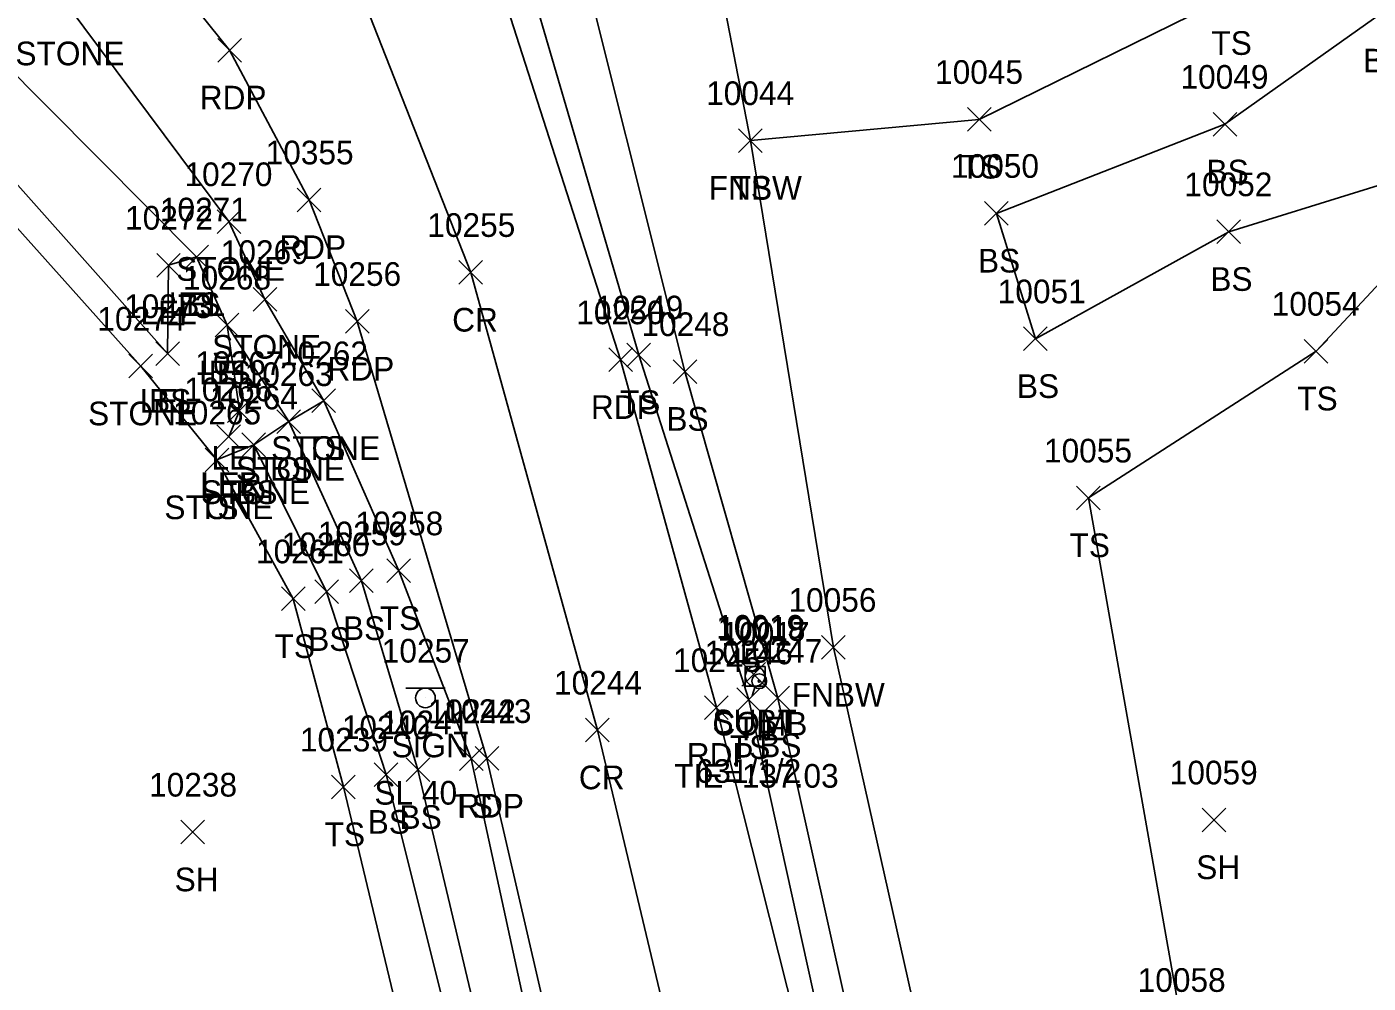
# Model space of a CAD drawing. Extents: x 1475671 to 1477951, y 592661 to 593821.
# Drawn here: x 1476827.5 to 1476940.9, y 592957 to 593037.8 of the extents above; entities that cross this region are included whole.
import ezdxf

# ---------------------------------------------------------------- set-up
doc = ezdxf.new("R2010")
doc.units = 0
for name, color, linetype in [('C_A', 7, 'Continuous'), ('C_C', 7, 'Continuous'), ('C_I', 7, 'Continuous'), ('CBP', 7, 'Continuous'), ('L_A', 7, 'Continuous'), ('L_I', 7, 'Continuous'), ('L_TIC', 7, 'Continuous'), ('LARO', 7, 'Continuous'), ('LASF', 7, 'Continuous'), ('LELB', 7, 'Continuous'), ('LFNC', 7, 'Continuous'), ('P_A', 7, 'Continuous'), ('P_I', 7, 'Continuous'), ('P_TIC', 7, 'Continuous'), ('PET', 7, 'Continuous'), ('PRC', 7, 'Continuous'), ('S_A', 7, 'Continuous'), ('S_C', 7, 'Continuous'), ('S_I', 7, 'Continuous'), ('SSGN', 7, 'Continuous'), ('U_A', 7, 'Continuous'), ('U_C', 7, 'Continuous'), ('U_I', 7, 'Continuous'), ('U_TIC', 7, 'Continuous'), ('UP', 7, 'Continuous')]:
    doc.layers.add(name, color=color, linetype=linetype)

msp = doc.modelspace()

# ---------------------------------------------------------------- linework, layer by layer
at = {"layer": 'CBP'}
for radius in [0.625, 0.0833]:
    msp.add_circle((1476889.41, 592982.47), radius, dxfattribs=at)
at = {"layer": 'L_TIC'}
for points in [[(1476907.01, 593028.94), (1476909.01, 593030.94)], [(1476909.01, 593028.94), (1476907.01, 593030.94)], [(1476927.77, 593028.53), (1476929.77, 593030.53)], [(1476929.77, 593028.53), (1476927.77, 593030.53)], [(1476887.66, 593027.15), (1476889.66, 593029.15)], [(1476889.66, 593027.15), (1476887.66, 593029.15)], [(1476887.66, 593027.15), (1476889.66, 593029.15)], [(1476889.66, 593027.15), (1476887.66, 593029.15)], [(1476843.58, 593020.3), (1476845.58, 593022.3)], [(1476845.58, 593020.3), (1476843.58, 593022.3)], [(1476908.46, 593021), (1476910.46, 593023)], [(1476910.46, 593021), (1476908.46, 593023)], [(1476928.1, 593019.45), (1476930.1, 593021.45)], [(1476930.1, 593019.45), (1476928.1, 593021.45)], [(1476840.85, 593017.32), (1476842.85, 593019.32)], [(1476842.85, 593017.32), (1476840.85, 593019.32)], [(1476840.85, 593017.32), (1476842.85, 593019.32)], [(1476842.85, 593017.32), (1476840.85, 593019.32)], [(1476838.47, 593016.62), (1476840.47, 593018.62)], [(1476840.47, 593016.62), (1476838.47, 593018.62)], [(1476846.62, 593013.72), (1476848.62, 593015.72)], [(1476848.62, 593013.72), (1476846.62, 593015.72)], [(1476843.42, 593011.56), (1476845.42, 593013.56)], [(1476845.42, 593011.56), (1476843.42, 593013.56)], [(1476843.42, 593011.56), (1476845.42, 593013.56)], [(1476845.42, 593011.56), (1476843.42, 593013.56)], [(1476911.75, 593010.4), (1476913.75, 593012.4)], [(1476913.75, 593010.4), (1476911.75, 593012.4)], [(1476838.39, 593009.15), (1476840.39, 593011.15)], [(1476840.39, 593009.15), (1476838.39, 593011.15)], [(1476838.39, 593009.15), (1476840.39, 593011.15)], [(1476840.39, 593009.15), (1476838.39, 593011.15)], [(1476878.22, 593009.04), (1476880.22, 593011.04)], [(1476880.22, 593009.04), (1476878.22, 593011.04)], [(1476935.48, 593009.35), (1476937.48, 593011.35)], [(1476937.48, 593009.35), (1476935.48, 593011.35)], [(1476836.13, 593008.09), (1476838.13, 593010.09)], [(1476838.13, 593008.09), (1476836.13, 593010.09)], [(1476882.12, 593007.63), (1476884.12, 593009.63)], [(1476884.12, 593007.63), (1476882.12, 593009.63)], [(1476844.46, 593004.34), (1476846.46, 593006.34)], [(1476846.46, 593004.34), (1476844.46, 593006.34)], [(1476851.6, 593005.17), (1476853.6, 593007.17)], [(1476853.6, 593005.17), (1476851.6, 593007.17)], [(1476851.6, 593005.17), (1476853.6, 593007.17)], [(1476853.6, 593005.17), (1476851.6, 593007.17)], [(1476851.6, 593005.17), (1476853.6, 593007.17)], [(1476853.6, 593005.17), (1476851.6, 593007.17)], [(1476848.63, 593003.41), (1476850.63, 593005.41)], [(1476850.63, 593003.41), (1476848.63, 593005.41)], [(1476848.63, 593003.41), (1476850.63, 593005.41)], [(1476850.63, 593003.41), (1476848.63, 593005.41)], [(1476843.57, 593002.12), (1476845.57, 593004.12)], [(1476845.57, 593002.12), (1476843.57, 593004.12)], [(1476843.57, 593002.12), (1476845.57, 593004.12)], [(1476845.57, 593002.12), (1476843.57, 593004.12)], [(1476845.68, 593001.44), (1476847.68, 593003.44)], [(1476847.68, 593001.44), (1476845.68, 593003.44)], [(1476845.68, 593001.44), (1476847.68, 593003.44)], [(1476847.68, 593001.44), (1476845.68, 593003.44)], [(1476842.57, 593000.16), (1476844.57, 593002.16)], [(1476844.57, 593000.16), (1476842.57, 593002.16)], [(1476842.57, 593000.16), (1476844.57, 593002.16)], [(1476844.57, 593000.16), (1476842.57, 593002.16)], [(1476916.23, 592996.95), (1476918.23, 592998.95)], [(1476918.23, 592996.95), (1476916.23, 592998.95)], [(1476857.93, 592990.8), (1476859.93, 592992.8)], [(1476859.93, 592990.8), (1476857.93, 592992.8)], [(1476854.78, 592989.95), (1476856.78, 592991.95)], [(1476856.78, 592989.95), (1476854.78, 592991.95)], [(1476851.83, 592989.03), (1476853.83, 592991.03)], [(1476853.83, 592989.03), (1476851.83, 592991.03)], [(1476849.02, 592988.43), (1476851.02, 592990.43)], [(1476851.02, 592988.43), (1476849.02, 592990.43)], [(1476894.68, 592984.33), (1476896.68, 592986.33)], [(1476896.68, 592984.33), (1476894.68, 592986.33)], [(1476887.52, 592979.9), (1476889.52, 592981.9)], [(1476889.52, 592979.9), (1476887.52, 592981.9)], [(1476889.97, 592980.04), (1476891.97, 592982.04)], [(1476891.97, 592980.04), (1476889.97, 592982.04)], [(1476864.07, 592974.92), (1476866.07, 592976.92)], [(1476866.07, 592974.92), (1476864.07, 592976.92)], [(1476859.55, 592973.99), (1476861.55, 592975.99)], [(1476861.55, 592973.99), (1476859.55, 592975.99)], [(1476856.87, 592973.58), (1476858.87, 592975.58)], [(1476858.87, 592973.58), (1476856.87, 592975.58)], [(1476853.26, 592972.53), (1476855.26, 592974.53)], [(1476855.26, 592972.53), (1476853.26, 592974.53)], [(1476926.86, 592969.75), (1476928.86, 592971.75)], [(1476928.86, 592969.75), (1476926.86, 592971.75)], [(1476840.5, 592968.72), (1476842.5, 592970.72)], [(1476842.5, 592968.72), (1476840.5, 592970.72)]]:
    msp.add_lwpolyline(points, dxfattribs=at)
at = {"layer": 'LARO'}
msp.add_lwpolyline([(1476844.57, 593003.12), (1476845.46, 593005.34), (1476844.42, 593012.56), (1476841.85, 593018.32), (1476839.47, 593017.62), (1476839.39, 593010.15)], dxfattribs=at)
at = {"layer": 'LASF'}
for points in [[(1476852.6, 593006.17), (1476849.63, 593004.41), (1476846.68, 593002.44), (1476843.57, 593001.16), (1476837.13, 593009.09), (1476818.53, 593029.85), (1476807.42, 593044.4), (1476779.57, 593058.62), (1476779.42, 593062.14), (1476780.76, 593069.19)], [(1476852.6, 593006.17), (1476847.62, 593014.72), (1476844.58, 593021.3), (1476830.99, 593039.51), (1476813.62, 593055.13), (1476780.76, 593069.19)]]:
    msp.add_lwpolyline(points, dxfattribs=at)
at = {"layer": 'LELB'}
for points in [[(1476841.85, 593018.32), (1476825.12, 593035.12), (1476811.51, 593051.32), (1476779.42, 593062.14), (1476752.49, 593064.9), (1476722.37, 593064.49), (1476691.91, 593057.79), (1476666.49, 593052.08), (1476661.25, 593053.21), (1476656.95, 593052.9), (1476655.98, 593055.35), (1476654.36, 593057.56), (1476652.4, 593057.3), (1476651.11, 593057.01), (1476646.46, 593054.41), (1476629, 593052.03), (1476594.01, 593046.66), (1476557.34, 593044.4), (1476521.14, 593041.18), (1476464.22, 593030.64)], [(1476839.39, 593010.15), (1476820.84, 593030.96), (1476810.95, 593047.74), (1476779.57, 593058.62), (1476752.41, 593061.01), (1476722.8, 593061.3), (1476693.96, 593054.33), (1476667.9, 593046.42), (1476659.43, 593048.7), (1476654.11, 593050.55), (1476650.93, 593054.11), (1476646.9, 593052.35), (1476629.79, 593048.23), (1476596.33, 593042), (1476591.8, 593026.06), (1476582.27, 593023.28), (1476575.03, 593016.09), (1476569.43, 592997.76), (1476547.37, 592959.22)], [(1476888.66, 593028.15), (1476908.01, 593029.94), (1476929.22, 593040.39), (1476951.33, 593056.02)], [(1476951.33, 593056.02), (1476942.02, 593038.91), (1476928.77, 593029.53), (1476909.46, 593022), (1476912.75, 593011.4), (1476929.1, 593020.45), (1476952.72, 593027.76)], [(1476945.37, 592716.49), (1476943.84, 592716.05), (1476935.5, 592756.29), (1476927.52, 592796.97), (1476921.14, 592836.68), (1476908.22, 592899.62), (1476901.04, 592935.89), (1476890.97, 592981.04), (1476883.12, 593008.63), (1476873.18, 593048.38)], [(1476947.68, 592723.33), (1476948.72, 592716.37), (1476942.58, 592713.1), (1476940.5, 592717.38), (1476933.16, 592755.58), (1476925.3, 592796.65), (1476917.94, 592836.99), (1476905.66, 592899.26), (1476898.49, 592935.73), (1476888.52, 592980.9), (1476879.22, 593010.04), (1476868.24, 593047.6)], [(1476952.72, 593027.76), (1476936.48, 593010.35), (1476917.23, 592997.95), (1476925.15, 592953.22), (1476941.06, 592913.44), (1476966.6, 592878.29), (1476971.99, 592843.21), (1476983.5, 592845.91), (1476990.36, 592866.95), (1477000.63, 592889.85)], [(1476884.44, 592847.94), (1476886.05, 592848.17), (1476877.95, 592894.89), (1476871.46, 592929.11), (1476860.55, 592974.99), (1476855.78, 592990.95), (1476849.63, 593004.41), (1476844.42, 593012.56)], [(1476879.49, 592846.47), (1476885.7, 592845.11), (1476890.61, 592848.98), (1476882.01, 592895.28), (1476874.91, 592930.53), (1476865.07, 592975.92), (1476858.93, 592991.8), (1476852.6, 593006.17)], [(1476884.44, 592847.94), (1476875.31, 592894.79), (1476869.54, 592928.01), (1476857.87, 592974.58), (1476852.83, 592990.03), (1476846.68, 593002.44)], [(1476879.49, 592846.47), (1476872.01, 592894.47), (1476865.51, 592926.72), (1476854.26, 592973.53), (1476850.02, 592989.43), (1476843.57, 593001.16)]]:
    msp.add_lwpolyline(points, dxfattribs=at)
at = {"layer": 'LFNC'}
msp.add_lwpolyline([(1476884.45, 593049.97), (1476888.66, 593028.15), (1476895.68, 592985.33), (1476904.01, 592948.27), (1476913.36, 592903.17), (1476920.67, 592866.25), (1476927.31, 592835.25), (1476934.4, 592801.93), (1476940.69, 592763.21), (1476947.68, 592723.33)], dxfattribs=at)
at = {"layer": 'P_TIC'}
for points in [[(1476843.63, 593034.78), (1476845.63, 593036.78)], [(1476845.63, 593034.78), (1476843.63, 593036.78)], [(1476850.35, 593022.14), (1476852.35, 593024.14)], [(1476852.35, 593022.14), (1476850.35, 593024.14)], [(1476864.02, 593016.01), (1476866.02, 593018.01)], [(1476866.02, 593016.01), (1476864.02, 593018.01)], [(1476854.42, 593011.87), (1476856.42, 593013.87)], [(1476856.42, 593011.87), (1476854.42, 593013.87)], [(1476876.69, 593008.63), (1476878.69, 593010.63)], [(1476878.69, 593008.63), (1476876.69, 593010.63)], [(1476884.79, 592979.24), (1476886.79, 592981.24)], [(1476886.79, 592979.24), (1476884.79, 592981.24)], [(1476874.73, 592977.34), (1476876.73, 592979.34)], [(1476876.73, 592977.34), (1476874.73, 592979.34)], [(1476865.39, 592974.94), (1476867.39, 592976.94)], [(1476867.39, 592974.94), (1476865.39, 592976.94)]]:
    msp.add_lwpolyline(points, dxfattribs=at)
at = {"layer": 'PET'}
for points in [[(1476948.05, 592670.97), (1476946.44, 592678.68), (1476938.73, 592716.33), (1476931.28, 592754.87), (1476923.71, 592796.39), (1476916.31, 592836.87), (1476904.07, 592899.01), (1476897.02, 592935.82), (1476885.79, 592980.24), (1476877.69, 593009.63), (1476865.86, 593046.37), (1476861.23, 593059.8), (1476852.05, 593085.53)], [(1476876.69, 592931.37), (1476866.39, 592975.94), (1476855.42, 593012.87), (1476851.35, 593023.14), (1476844.63, 593035.78), (1476834.27, 593048.7), (1476823.42, 593058.99), (1476807.6, 593067.92), (1476802.87, 593070.05), (1476785.81, 593074.83), (1476762.31, 593077.35), (1476735.17, 593076.04), (1476692.75, 593070.03), (1476654.27, 593063.28), (1476593.38, 593051.4), (1476557.14, 593047.34), (1476521.33, 593044.37), (1476462.5, 593038.2)]]:
    msp.add_lwpolyline(points, dxfattribs=at)
at = {"layer": 'PRC'}
msp.add_lwpolyline([(1476936.41, 592672.33), (1476928.58, 592713.02), (1476920.34, 592755.64), (1476913.25, 592793.06), (1476905.79, 592835.15), (1476893.85, 592896.99), (1476886.39, 592933.64), (1476875.73, 592978.34), (1476865.02, 593017.01), (1476853.41, 593046.52), (1476843.49, 593055.1), (1476828.74, 593067.47), (1476810.85, 593077.22), (1476783.7, 593084.94)], dxfattribs=at)
at = {"layer": 'SSGN'}
for p, q in [((1476859.54, 592981.89), (1476862.87, 592981.89)), ((1476861.19, 592981.06), (1476861.19, 592981.06))]:
    msp.add_line(p, q, dxfattribs=at)
msp.add_circle((1476861.19, 592981.06), 0.833, dxfattribs=at)
at = {"layer": 'U_TIC'}
for points in [[(1476887.95, 592982.06), (1476889.95, 592984.06)], [(1476889.95, 592982.06), (1476887.95, 592984.06)]]:
    msp.add_lwpolyline(points, dxfattribs=at)
at = {"layer": 'UP'}
for p, q in [((1476888.23, 592982.05), (1476888.23, 592983.72)), ((1476888.23, 592983.72), (1476889.9, 592983.72)), ((1476889.31, 592984.55), (1476889.06, 592983.72)), ((1476889.9, 592983.72), (1476889.9, 592982.05)), ((1476889.06, 592982.88), (1476889.06, 592982.88)), ((1476889.9, 592982.05), (1476888.23, 592982.05)), ((1476888.81, 592981.22), (1476889.06, 592982.05))]:
    msp.add_line(p, q, dxfattribs=at)
msp.add_circle((1476889.06, 592982.88), 0.833, dxfattribs=at)

# ---------------------------------------------------------------- texts
at = {"layer": 'C_A'}
msp.add_text('TIE', height=2, dxfattribs=at).set_placement((1476887.48, 592977.47))
at = {"layer": 'C_C'}
msp.add_text('TIE=137.03', height=2, dxfattribs=at).set_placement((1476882.22, 592973.47))
at = {"layer": 'C_I'}
msp.add_text('10017', height=2, dxfattribs=at).set_placement((1476886.22, 592985.47))
at = {"layer": 'L_A'}
for s, p in [('TS', (1476927.63, 593035.39)), ('STONE', (1476826.53, 593034.51)), ('BS', (1476940.46, 593033.91)), ('TS', (1476906.42, 593024.94)), ('BS', (1476927.22, 593024.53)), ('FNBW', (1476885.14, 593023.15)), ('TS', (1476887.07, 593023.15)), ('BS', (1476907.9, 593017)), ('STONE', (1476840.12, 593016.3)), ('BS', (1476927.54, 593015.45)), ('LEL', (1476837.1, 593012.62)), ('LEL', (1476839.48, 593013.32)), ('BS', (1476840.29, 593013.32)), ('STONE', (1476843.16, 593009.72)), ('LEL', (1476842.06, 593007.56)), ('BS', (1476842.86, 593007.56)), ('BS', (1476911.19, 593006.4)), ('LEL', (1476837.03, 593005.15)), ('BS', (1476837.83, 593005.15)), ('TS', (1476877.63, 593005.04)), ('TS', (1476934.89, 593005.35)), ('STONE', (1476832.67, 593004.09)), ('BS', (1476881.56, 593003.63)), ('STONE', (1476848.15, 593001.17)), ('STONE', (1476848.15, 593001.17)), ('TS', (1476851.01, 593001.17)), ('LEL', (1476843.1, 593000.34)), ('STONE', (1476845.17, 592999.41)), ('BS', (1476848.07, 592999.41)), ('LER', (1476842.15, 592998.12)), ('LEL', (1476842.21, 592998.12)), ('STONE', (1476842.22, 592997.44)), ('BS', (1476845.12, 592997.44)), ('STONE', (1476839.12, 592996.16)), ('TS', (1476841.98, 592996.16)), ('TS', (1476915.64, 592992.95)), ('TS', (1476857.34, 592986.8)), ('BS', (1476851.28, 592985.03)), ('BS', (1476854.22, 592985.95)), ('TS', (1476848.43, 592984.43)), ('FNBW', (1476892.15, 592980.33)), ('BS', (1476889.41, 592976.04)), ('TS', (1476886.93, 592975.9)), ('TS', (1476863.48, 592970.92)), ('BS', (1476856.31, 592969.58)), ('BS', (1476859, 592969.99)), ('TS', (1476852.67, 592968.53)), ('SH', (1476926.35, 592965.75)), ('SH', (1476839.99, 592964.72))]:
    msp.add_text(s, height=2, dxfattribs=at).set_placement(p)
at = {"layer": 'L_I'}
for s, p in [('10045', (1476904.27, 593032.94)), ('10049', (1476925.02, 593032.53)), ('10044', (1476884.92, 593031.15)), ('10044', (1476884.92, 593031.15)), ('10050', (1476905.62, 593025)), ('10270', (1476840.82, 593024.3)), ('10052', (1476925.35, 593023.45)), ('10271', (1476838.74, 593021.32)), ('10271', (1476838.74, 593021.32)), ('10272', (1476835.8, 593020.62)), ('10269', (1476843.89, 593017.72)), ('10268', (1476840.7, 593015.56)), ('10268', (1476840.7, 593015.56)), ('10051', (1476909.57, 593014.4)), ('10273', (1476835.72, 593013.15)), ('10273', (1476835.72, 593013.15)), ('10249', (1476875.55, 593013.04)), ('10054', (1476932.73, 593013.35)), ('10274', (1476833.46, 593012.09)), ('10248', (1476879.45, 593011.63)), ('10262', (1476848.89, 593009.17)), ('10262', (1476848.89, 593009.17)), ('10262', (1476848.89, 593009.17)), ('10267', (1476841.74, 593008.34)), ('10263', (1476845.91, 593007.41)), ('10263', (1476845.91, 593007.41)), ('10266', (1476840.8, 593006.12)), ('10266', (1476840.8, 593006.12)), ('10264', (1476842.97, 593005.44)), ('10264', (1476842.97, 593005.44)), ('10265', (1476839.86, 593004.16)), ('10265', (1476839.86, 593004.16)), ('10055', (1476913.48, 593000.95)), ('10258', (1476855.26, 592994.8)), ('10260', (1476849.03, 592993.03)), ('10259', (1476852.1, 592993.95)), ('10261', (1476846.87, 592992.43)), ('10056', (1476891.88, 592988.33)), ('10246', (1476884.8, 592983.9)), ('10247', (1476887.3, 592984.04)), ('10242', (1476861.4, 592978.92)), ('10240', (1476854.12, 592977.58)), ('10241', (1476857.45, 592977.99)), ('10239', (1476850.58, 592976.53)), ('10059', (1476924.11, 592973.75)), ('10238', (1476837.83, 592972.72)), ('10058', (1476921.4, 592956.22))]:
    msp.add_text(s, height=2, dxfattribs=at).set_placement(p)
at = {"layer": 'P_A'}
for s, p in [('RDP', (1476842.11, 593030.78)), ('RDP', (1476848.84, 593018.14)), ('CR', (1476863.45, 593012.01)), ('RDP', (1476852.91, 593007.87)), ('RDP', (1476875.18, 593004.63)), ('RDP', (1476883.28, 592975.24)), ('CR', (1476874.16, 592973.34)), ('RDP', (1476863.87, 592970.94))]:
    msp.add_text(s, height=2, dxfattribs=at).set_placement(p)
at = {"layer": 'P_I'}
for s, p in [('10355', (1476847.68, 593026.14)), ('10255', (1476861.35, 593020.01)), ('10256', (1476851.7, 593015.87)), ('10250', (1476873.94, 593012.63)), ('10245', (1476882.12, 592983.24)), ('10244', (1476872.06, 592981.34)), ('10243', (1476862.72, 592978.94))]:
    msp.add_text(s, height=2, dxfattribs=at).set_placement(p)
at = {"layer": 'S_A'}
msp.add_text('SIGN', height=2, dxfattribs=at).set_placement((1476858.32, 592976.04))
at = {"layer": 'S_C'}
msp.add_text('SL 40', height=2, dxfattribs=at).set_placement((1476856.88, 592972.04))
at = {"layer": 'S_I'}
msp.add_text('10257', height=2, dxfattribs=at).set_placement((1476857.5, 592984.04))
at = {"layer": 'U_A'}
for s, p in [('SUBT', (1476885.45, 592978.06)), ('COMB', (1476885.45, 592977.88))]:
    msp.add_text(s, height=2, dxfattribs=at).set_placement(p)
at = {"layer": 'U_C'}
msp.add_text('631/1/2', height=2, dxfattribs=at).set_placement((1476884.04, 592973.88))
at = {"layer": 'U_I'}
for s, p in [('10019', (1476885.77, 592986.06)), ('10018', (1476885.88, 592985.88))]:
    msp.add_text(s, height=2, dxfattribs=at).set_placement(p)

doc.saveas('drawing.dxf')
